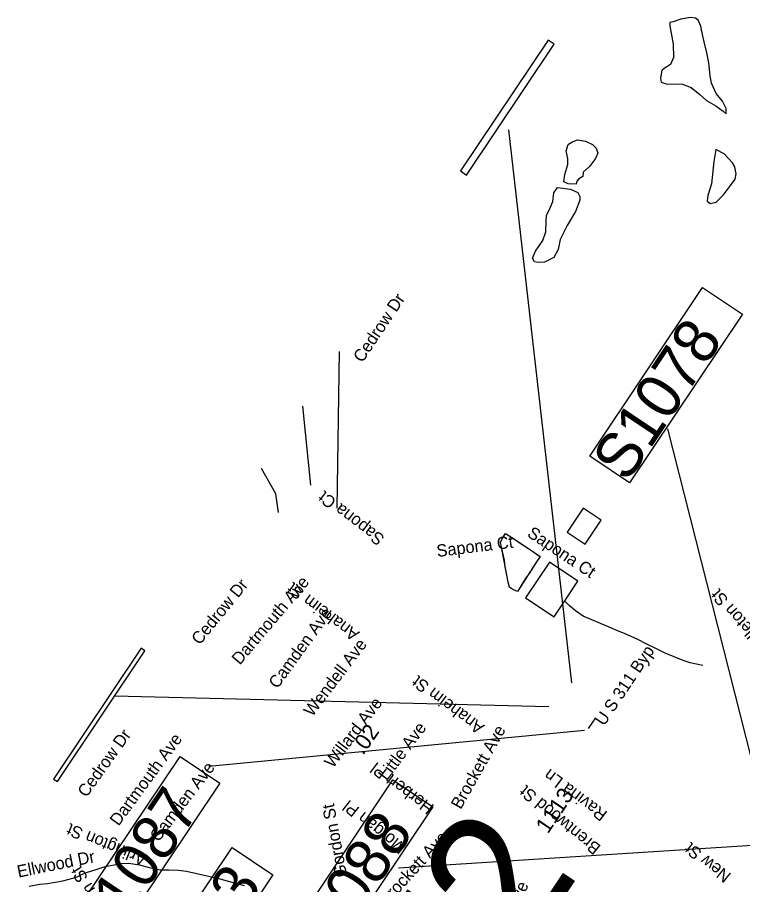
# Model space of a CAD drawing. Extents: x 1716282 to 1717158, y 799307 to 801078.
# Drawn here: x 1716526.3 to 1716608.3, y 799484.2 to 799582.2 of the extents above; entities that cross this region are included whole.
import ezdxf

# ---------------------------------------------------------------- set-up
doc = ezdxf.new("R2010")
doc.units = 0
for name, color, linetype in [('Exist Hydrographic Misc Water Feature', 7, 'Continuous'), ('Exist Hydrographic Pond Under 1500 Sq Ft', 7, 'Continuous'), ('Exist Road Non-System Structure Non-Sys NCDOT Number Label', 7, 'Continuous'), ('Exist Road Non-System Structure Non-Sys Other Number Label', 7, 'Continuous'), ('Exist Road Non-System Type 51 Label', 7, 'Continuous'), ('Exist Road Primary Interstate Structure Cantilever Sign Number Label', 7, 'Continuous'), ('Exist Road Primary US Structure Ovrhead Sign CELL', 7, 'Continuous'), ('Exist Road Primary US Structure Standard Bridge Number Label', 7, 'Continuous'), ('Exist Road Secondary Mileage Hundredths English Label', 7, 'Continuous'), ('Exist Road Secondary Structure Standard Bridge Number Label', 7, 'Continuous'), ('Exist Road Secondary Type 51 Number Label', 7, 'Continuous')]:
    doc.layers.add(name, color=color, linetype=linetype)

msp = doc.modelspace()

# ---------------------------------------------------------------- linework, layer by layer
at = {"layer": 'Exist Hydrographic Misc Water Feature'}
for points in [[(1716555.828, 799526.221), (1716555.508, 799528.337), (1716553.886, 799531.191)], [(1716588.459, 799524.011), (1716590.487, 799522.66), (1716592.296, 799525.36), (1716590.269, 799526.711), (1716588.459, 799524.011)], [(1716588.459, 799524.011), (1716590.487, 799522.66), (1716592.296, 799525.36), (1716590.269, 799526.711), (1716588.459, 799524.011)], [(1716581.474, 799523.864), (1716582.496, 799523.201), (1716583.263, 799522.678), (1716583.95, 799522.245), (1716584.669, 799521.753), (1716585.107, 799521.418), (1716585.388, 799521.262), (1716584.921, 799520.528), (1716584.224, 799519.456), (1716583.75, 799518.761), (1716583.235, 799517.956), (1716583.012, 799517.581), (1716582.839, 799517.276), (1716582.567, 799517.392), (1716582.215, 799517.597), (1716581.952, 799517.777), (1716581.781, 799518.349), (1716581.592, 799519.357), (1716581.456, 799520.084), (1716581.359, 799520.816), (1716581.26, 799521.34), (1716581.068, 799522.139), (1716580.983, 799522.479), (1716580.953, 799522.64), (1716580.916, 799522.842), (1716581.08, 799523.185), (1716581.334, 799523.609), (1716581.474, 799523.864)], [(1716581.474, 799523.864), (1716582.496, 799523.201), (1716583.95, 799522.245), (1716584.669, 799521.753), (1716585.388, 799521.262), (1716584.921, 799520.528), (1716582.839, 799517.276), (1716582.567, 799517.392), (1716582.215, 799517.597), (1716581.952, 799517.777), (1716581.781, 799518.349), (1716580.983, 799522.479), (1716580.953, 799522.64), (1716580.916, 799522.842), (1716581.08, 799523.185), (1716581.474, 799523.864)], [(1716588.171, 799516.235), (1716589.668, 799518.478), (1716586.449, 799520.606), (1716583.724, 799516.565), (1716586.967, 799514.42), (1716588.171, 799516.235)], [(1716588.171, 799516.235), (1716589.668, 799518.478), (1716586.449, 799520.606), (1716583.724, 799516.565), (1716586.967, 799514.42), (1716588.171, 799516.235)], [(1716603.802, 799508.929), (1716602.348, 799509.218), (1716601.547, 799509.485), (1716599.53, 799510.337), (1716598.632, 799510.772), (1716597.393, 799511.376), (1716596.44, 799511.885), (1716594.919, 799512.538), (1716594.31, 799512.777), (1716592.925, 799513.373), (1716590.268, 799514.522), (1716589.381, 799515.126), (1716588.663, 799515.721), (1716588.225, 799516.161), (1716588.171, 799516.235)], [(1716527.656, 799484.011), (1716528.865, 799484.238), (1716529.727, 799484.317), (1716531.444, 799484.619), (1716532.582, 799484.897), (1716533.051, 799485.068), (1716533.568, 799485.312), (1716534.109, 799485.538), (1716535.329, 799485.935), (1716536.216, 799486.206), (1716536.838, 799486.345), (1716537.241, 799486.421), (1716538.071, 799486.555), (1716538.901, 799486.587), (1716540.106, 799486.396), (1716541.205, 799486.102), (1716542.481, 799485.863), (1716543.445, 799485.835), (1716544.54, 799485.793), (1716545.431, 799485.708), (1716548.946, 799484.888), (1716550.968, 799484.35), (1716551.939, 799484.074)]]:
    msp.add_lwpolyline(points, dxfattribs=at)
at = {"layer": 'Exist Hydrographic Pond Under 1500 Sq Ft'}
for points in [[(1716601.297, 799581.952), (1716600.447, 799581.67), (1716600.066, 799581.595), (1716600.054, 799581.225), (1716600.442, 799579.122), (1716600.483, 799577.63), (1716600.133, 799576.825), (1716599.424, 799576.401), (1716599.162, 799576.151), (1716599.019, 799575.302), (1716599.083, 799574.833), (1716599.627, 799574.658), (1716601.5, 799574.633), (1716602.457, 799574.229), (1716603.436, 799573.432), (1716604.218, 799572.767), (1716605.273, 799572.155), (1716606.1, 799571.555), (1716606.415, 799571.249), (1716606.405, 799571.87), (1716606.015, 799572.698), (1716605.276, 799573.571), (1716604.767, 799574.715), (1716604.627, 799575.565), (1716604.478, 799577.035), (1716604.229, 799578.147), (1716603.927, 799579.389), (1716603.733, 799580.228), (1716603.571, 799581.186), (1716603.268, 799581.862), (1716602.974, 799582.058), (1716602.387, 799582.168), (1716601.297, 799581.952)], [(1716589.466, 799563.311), (1716588.557, 799563.34), (1716588.09, 799563.594), (1716588.172, 799564.41), (1716588.535, 799565.559), (1716588.51, 799566.215), (1716588.338, 799567.084), (1716588.58, 799567.792), (1716588.942, 799568.072), (1716589.624, 799568.312), (1716590.519, 799568.177), (1716591.321, 799567.815), (1716591.721, 799567.373), (1716591.933, 799566.824), (1716591.638, 799566.21), (1716590.981, 799565.315), (1716590.271, 799564.687), (1716590.23, 799564.193), (1716589.762, 799563.926), (1716589.534, 799563.672), (1716589.466, 799563.311)], [(1716607.151, 799565.745), (1716606.194, 799566.728), (1716605.27, 799567.248), (1716605.041, 799565.883), (1716604.777, 799563.368), (1716604.368, 799562.026), (1716604.287, 799561.394), (1716604.603, 799561.134), (1716605.28, 799561.268), (1716606.139, 799562.113), (1716606.897, 799563.173), (1716607.429, 799563.894), (1716607.543, 799564.503), (1716607.42, 799565.27), (1716607.151, 799565.745)], [(1716587.353, 799562.927), (1716588.81, 799562.764), (1716589.652, 799562.375), (1716589.878, 799561.934), (1716589.891, 799561.519), (1716589.38, 799560.236), (1716588.441, 799558.66), (1716587.676, 799557.083), (1716587.419, 799555.921), (1716586.936, 799555.025), (1716585.892, 799554.506), (1716585.237, 799554.48), (1716584.769, 799554.561), (1716584.516, 799554.963), (1716584.879, 799555.764), (1716585.683, 799556.966), (1716586.046, 799557.942), (1716586.089, 799559.132), (1716586.104, 799559.76), (1716586.52, 799560.642), (1716586.829, 799561.364), (1716586.951, 799562.326), (1716587.353, 799562.927)]]:
    msp.add_lwpolyline(points, dxfattribs=at)
at = {"layer": 'Exist Road Non-System Structure Non-Sys NCDOT Number Label'}
msp.add_line((1716559.473, 799529.31), (1716558.589, 799538.217), dxfattribs=at)
at = {"layer": 'Exist Road Primary Interstate Structure Cantilever Sign Number Label'}
msp.add_line((1716562.452, 799526.709), (1716562.727, 799544.4), dxfattribs=at)
at = {"layer": 'Exist Road Primary US Structure Ovrhead Sign CELL'}
for p, q in [((1716610.75, 799492.574), (1716599.832, 799535.666)), ((1716590.879, 799501.808), (1716591.695, 799503.027)), ((1716590.422, 799501.574), (1716547.955, 799497.512)), ((1716610.601, 799488.678), (1716569.402, 799486.024))]:
    msp.add_line(p, q, dxfattribs=at)
for points in [[(1716591, 799532.601), (1716603.743, 799551.64), (1716608.251, 799548.623), (1716595.508, 799529.584)], [(1716531.957, 799479.624), (1716544.7, 799498.663), (1716549.209, 799495.645), (1716536.466, 799476.606)], [(1716556.007, 799476.96), (1716568.75, 799495.999), (1716573.259, 799492.981), (1716560.516, 799473.942)]]:
    msp.add_lwpolyline(points, close=True, dxfattribs=at)
at = {"layer": 'Exist Road Primary US Structure Standard Bridge Number Label'}
for p, q in [((1716586.288, 799579.602), (1716576.387, 799564.809)), ((1716588.987, 799506.982), (1716581.868, 799569.451)), ((1716540.302, 799510.895), (1716530.4, 799496.102)), ((1716586.393, 799504.269), (1716537.288, 799505.483))]:
    msp.add_line(p, q, dxfattribs=at)
for points in [[(1716576.387, 799564.809), (1716577.079, 799564.346), (1716586.98, 799579.139), (1716586.288, 799579.602)], [(1716530.4, 799496.102), (1716530.833, 799495.812), (1716540.734, 799510.605), (1716540.302, 799510.895)]]:
    msp.add_lwpolyline(points, dxfattribs=at)
at = {"layer": 'Exist Road Secondary Structure Standard Bridge Number Label'}
msp.add_lwpolyline([(1716545.397, 799480.61), (1716550.592, 799488.372), (1716555.199, 799485.289), (1716550.004, 799477.527)], close=True, dxfattribs=at)

# ---------------------------------------------------------------- texts
at = {"layer": 'Exist Road Non-System Structure Non-Sys Other Number Label'}
msp.add_text('J572', height=15.223, rotation=56.20506, dxfattribs=at).set_placement((1716565.359, 799448.751))
at = {"layer": 'Exist Road Non-System Type 51 Label'}
for s, rotation, p in [('Cedrow Dr', 56.20506, (1716565.309, 799543.071)), ('Sapona Ct', 142.62575, (1716567.914, 799523.465)), ('Sapona Ct', 326.30074, (1716583.832, 799523.588)), ('Sapona Ct', 7.04168, (1716573.779, 799521.187)), ('Cedrow Dr', 50.85121, (1716546.919, 799511.179)), ('Dartmouth Ave', 49.82826, (1716551.455, 799508.916)), ('Anaheim St', 143.02705, (1716565.067, 799512.683)), ('Pendleton St', 131.39608, (1716612.577, 799509.8)), ('Camden Ave', 53.94463, (1716555.703, 799506.232)), ('Wendell Ave', 52.8762, (1716559.65, 799503.062)), ('U S 311 Byp', 56.20506, (1716592.631, 799502.019)), ('Anaheim St', 143.02705, (1716579.197, 799502.154)), ('Willard Ave', 52.70168, (1716561.987, 799497.263)), ('Little Ave', 53.0635, (1716568.063, 799495.833)), ('Cedrow Dr', 54.40632, (1716534.121, 799493.945)), ('Brockett Ave', 60.58419, (1716576.426, 799492.593)), ('Dartmouth Ave', 53.74902, (1716537.749, 799490.716)), ('Camden Ave', 52.74264, (1716542.264, 799488.913)), ('Herbert Pl', 142.98682, (1716573.513, 799493.098)), ('Ravina Ln', 142.92525, (1716593.099, 799492.333)), ('Brentwood St', 140.73082, (1716592.353, 799488.507)), ('Morgan Pl', 141.56564, (1716570.369, 799488.593)), ('Gordon St', 100.32997, (1716563.594, 799485.137)), ('Arlington St', 157.66405, (1716541.057, 799487.517)), ('Brockett Ave', 47.72572, (1716568.048, 799481.69)), ('New St', 141.70343, (1716607.081, 799485.352)), ('Ellwood Dr', 11.42594, (1716526.432, 799484.958)), ('Ashburn St', 122.07806, (1716538.264, 799478.707)), ('Lamb Ave', 66.98068, (1716580.885, 799476.534))]:
    msp.add_text(s, height=1.3775, rotation=rotation, dxfattribs=at).set_placement(p)
at = {"layer": 'Exist Road Primary US Structure Ovrhead Sign CELL'}
for s, p in [('S1078', (1716595.239, 799529.483)), ('S1087', (1716536.196, 799476.506)), ('S1088', (1716560.246, 799473.842))]:
    msp.add_text(s, height=5.075, rotation=56.20506, dxfattribs=at).set_placement(p)
at = {"layer": 'Exist Road Secondary Mileage Hundredths English Label'}
msp.add_text('.02', height=1.8125, rotation=55.30053, dxfattribs=at).set_placement((1716565.383, 799498.709))
at = {"layer": 'Exist Road Secondary Structure Standard Bridge Number Label'}
msp.add_text('13', height=5.075, rotation=56.20506, dxfattribs=at).set_placement((1716549.867, 799477.838))
at = {"layer": 'Exist Road Secondary Type 51 Number Label'}
msp.add_text('1113', height=1.8125, rotation=56.20506, dxfattribs=at).set_placement((1716586.273, 799489.832))

doc.saveas('drawing.dxf')
